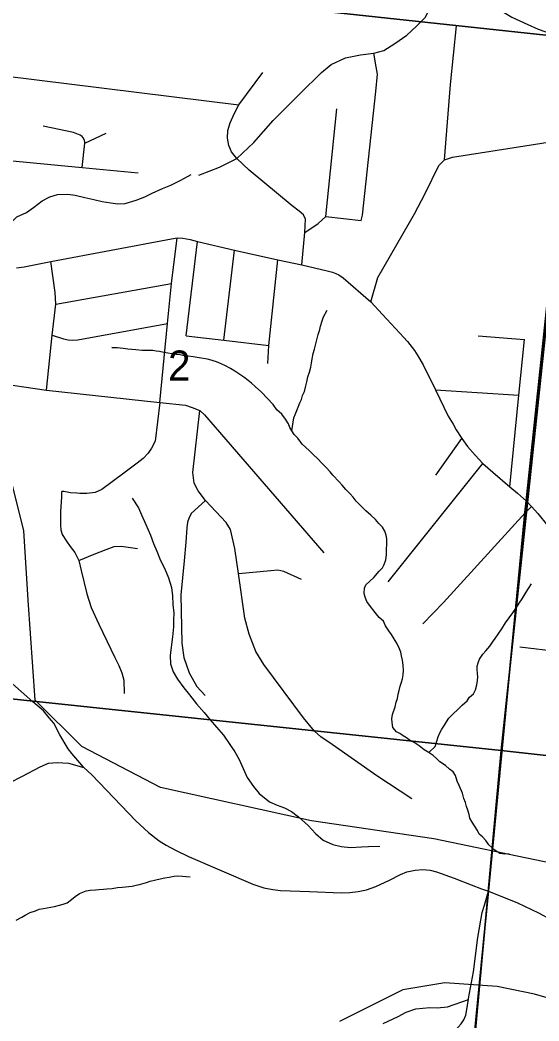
# Model space of a CAD drawing. Extents: x 0 to 34, y -2 to 22.
# Drawn here: x 6.671 to 7.396, y 18.207 to 19.604 of the extents above; entities that cross this region are included whole.
import ezdxf

# ---------------------------------------------------------------- set-up
doc = ezdxf.new("R2010")
doc.units = 0
for name, color, linetype in [('GM_X_City_Street', 7, 'Continuous'), ('GM_X_County_Road', 7, 'Continuous'), ('GM_X_Minor_River', 7, 'Continuous'), ('GM_X_Rail_Line', 7, 'Continuous'), ('GM_X_Section', 7, 'Continuous'), ('GM_X_Section_Text', 7, 'Continuous')]:
    doc.layers.add(name, color=color, linetype=linetype)

msp = doc.modelspace()

# ---------------------------------------------------------------- linework, layer by layer
at = {"layer": 'GM_X_City_Street'}
for p, q in [((7.0985, 19.3299), (7.1136, 19.4802)), ((6.7617, 19.4323), (6.7918, 19.4466)), ((6.9033, 19.1636), (6.9193, 19.2953)), ((6.9559, 19.1575), (6.9709, 19.2831)), ((6.7212, 19.208), (6.883, 19.2366)), ((7.3112, 19.1638), (7.376, 19.1583)), ((7.2517, 19.0883), (7.3679, 19.0806)), ((7.252, 18.9691), (7.2882, 19.0205)), ((7.1852, 18.8201), (7.3176, 18.9854)), ((7.4238, 18.7225), (7.3693, 18.729))]:
    msp.add_line(p, q, dxfattribs=at)
for points in [[(6.9742, 19.4112), (6.998, 19.4336), (7.0249, 19.464), (7.0622, 19.5013), (7.0924, 19.5313), (7.1056, 19.5424), (7.1256, 19.5517), (7.1468, 19.5559), (7.1652, 19.558), (7.1795, 19.562), (7.1948, 19.5714), (7.2114, 19.5834), (7.2252, 19.5956), (7.2369, 19.6078), (7.2495, 19.6321), (7.2627, 19.6641), (7.2673, 19.6719), (7.273, 19.6823)], [(6.4627, 19.5973), (6.4962, 19.5486), (6.4984, 19.547), (6.5001, 19.546), (6.5046, 19.5445), (6.5064, 19.5442), (6.9768, 19.4858)], [(7.2641, 19.4091), (7.2726, 19.5144), (7.2808, 19.5962)], [(7.1475, 19.3247), (7.1498, 19.3321), (7.168, 19.5045), (7.1706, 19.5287), (7.1688, 19.5392), (7.1652, 19.558)], [(7.0648, 19.2626), (7.069, 19.3078), (7.07, 19.3264), (7.067, 19.3325), (7.0612, 19.3377), (7.0515, 19.345), (6.9914, 19.3949), (6.9742, 19.4112), (6.9664, 19.4205), (6.9631, 19.4293), (6.9611, 19.4394), (6.9615, 19.4502), (6.9646, 19.4607), (6.9707, 19.4743), (6.9768, 19.4858), (7.0102, 19.5311)], [(6.758, 19.3985), (6.7617, 19.4323), (6.7618, 19.4334), (6.7613, 19.4366), (6.7597, 19.4399), (6.7583, 19.4419), (6.7552, 19.4438), (6.7458, 19.4475), (6.7035, 19.4561)], [(6.4991, 19.4022), (6.561, 19.4156), (6.5659, 19.4165), (6.5678, 19.4166), (6.583, 19.415), (6.656, 19.4082), (6.758, 19.3985), (6.8364, 19.3911)], [(6.9212, 19.3877), (6.95, 19.399), (6.9742, 19.4112)], [(7.069, 19.3078), (7.0876, 19.3204), (7.0985, 19.3299), (7.1475, 19.3247)], [(6.8667, 19.0705), (6.8771, 19.1808), (6.883, 19.2366), (6.8908, 19.3002)], [(6.7081, 19.0876), (6.7164, 19.1646), (6.7212, 19.208), (6.7205, 19.2239), (6.7144, 19.2672)], [(7.0174, 19.1251), (7.0189, 19.1501), (7.0314, 19.2698)], [(6.7164, 19.1646), (6.732, 19.1594), (6.7384, 19.1582), (6.7444, 19.1577), (6.7522, 19.1581), (6.8771, 19.1808)], [(6.9033, 19.1636), (6.9559, 19.1575), (7.0189, 19.1501)], [(7.3551, 18.953), (7.3679, 19.0806), (7.376, 19.1583)], [(6.6319, 19.0989), (6.7081, 19.0876), (6.8667, 19.0705), (6.9023, 19.0666), (6.9119, 19.0637), (6.9222, 19.0595), (6.929, 19.0535), (7.0954, 18.8607)], [(6.8667, 19.0705), (6.8599, 19.0164), (6.8548, 19.0067), (6.8502, 18.9999), (6.8431, 18.9925), (6.835, 18.986), (6.8162, 18.972), (6.7857, 18.9492), (6.7763, 18.9451), (6.7645, 18.9434), (6.755, 18.9437), (6.7504, 18.9438), (6.7417, 18.9445), (6.7327, 18.9462), (6.7298, 18.9464), (6.729, 18.9454), (6.7292, 18.9438), (6.729, 18.9391), (6.728, 18.9179), (6.7277, 18.8993), (6.7281, 18.8929), (6.73, 18.8863), (6.7361, 18.8772), (6.7411, 18.8696), (6.7478, 18.861), (6.7533, 18.8502), (6.7565, 18.8362), (6.7644, 18.8036), (6.7707, 18.7846), (6.7813, 18.761), (6.8039, 18.7145), (6.8093, 18.7034), (6.8136, 18.6931), (6.8161, 18.6831), (6.8167, 18.6645)], [(7.2183, 18.5175), (7.1696, 18.5495), (7.1071, 18.5934), (7.0916, 18.6041), (7.0827, 18.6117), (7.0672, 18.6306), (7.0116, 18.7047), (7.0007, 18.7232), (6.9913, 18.7473), (6.9854, 18.7694), (6.9765, 18.8319), (6.9714, 18.8666), (6.9653, 18.8933), (6.9594, 18.9033), (6.9302, 18.934), (6.9202, 18.9471), (6.9146, 18.9578), (6.9127, 18.9729), (6.9222, 19.0595)], [(6.9302, 18.934), (6.9102, 18.9158), (6.9071, 18.9086), (6.9054, 18.9034), (6.9042, 18.8955), (6.9029, 18.8756), (6.9003, 18.8497), (6.896, 18.802), (6.8972, 18.7348), (6.9002, 18.7149), (6.9077, 18.6933), (6.9183, 18.674), (6.9298, 18.6617)], [(7.2336, 18.7618), (7.2627, 18.7914), (7.3767, 18.9165), (7.3857, 18.9254)], [(6.7533, 18.8502), (6.7747, 18.859), (6.7918, 18.8656), (6.8026, 18.8697), (6.8125, 18.87), (6.8352, 18.8667)], [(6.9765, 18.8319), (7.0214, 18.8363), (7.0312, 18.8368), (7.0355, 18.8363), (7.0392, 18.8351), (7.0639, 18.8238)], [(7.1783, 18.204), (7.1995, 18.2138), (7.2106, 18.2198), (7.2239, 18.2242), (7.2435, 18.2263), (7.2539, 18.2259), (7.2681, 18.227), (7.2974, 18.2376)]]:
    msp.add_lwpolyline(points, dxfattribs=at)
at = {"layer": 'GM_X_County_Road'}
for points in [[(7.3332, 19.6234), (7.3367, 19.6212), (7.358, 19.6082), (7.3805, 19.5981), (7.3948, 19.5917), (7.4121, 19.5856), (7.4378, 19.5807), (7.4469, 19.5805), (7.4654, 19.58)], [(7.1611, 19.2111), (7.171, 19.245), (7.2064, 19.3063), (7.2223, 19.3338), (7.2372, 19.3621), (7.256, 19.4011), (7.2598, 19.4051), (7.2641, 19.4091), (7.2753, 19.413), (7.4149, 19.4349), (7.4318, 19.4376), (7.4347, 19.4382)], [(6.6662, 19.2586), (6.6771, 19.26), (6.7144, 19.2672), (6.883, 19.299), (6.8908, 19.3002), (6.8987, 19.3001), (6.909, 19.2978), (6.9193, 19.2953), (6.9709, 19.2831), (7.0314, 19.2698), (7.0648, 19.2626), (7.1001, 19.2545), (7.1078, 19.2525), (7.1122, 19.2508), (7.1164, 19.2488), (7.1224, 19.2446), (7.1611, 19.2111), (7.1773, 19.1932), (7.2018, 19.1672), (7.2124, 19.1556), (7.2221, 19.143), (7.227, 19.1355), (7.2343, 19.1231), (7.2517, 19.0883), (7.2693, 19.0517), (7.276, 19.0402), (7.2806, 19.0324), (7.2882, 19.0205), (7.2964, 19.0091), (7.3067, 18.9969), (7.3176, 18.9854), (7.3318, 18.9732), (7.3551, 18.953), (7.3659, 18.9438), (7.3784, 18.9328), (7.3857, 18.9254)], [(6.7603, 18.5613), (6.7435, 18.5806), (6.7385, 18.587), (6.7271, 18.6067), (6.7185, 18.6232), (6.7122, 18.6306), (6.7042, 18.6402), (6.6894, 18.6529), (6.6115, 18.7214), (6.6091, 18.7254), (6.6065, 18.7305), (6.6048, 18.735), (6.6027, 18.7411), (6.6011, 18.7465), (6.6001, 18.7509), (6.5985, 18.7586), (6.5988, 18.7676), (6.6004, 18.7792), (6.6087, 18.8604), (6.6319, 19.0989), (6.6381, 19.1562), (6.6503, 19.2574)], [(7.3857, 18.9254), (7.3945, 18.9158), (7.4079, 18.8991)], [(6.6565, 18.5396), (6.6748, 18.5491), (6.6995, 18.5623), (6.7111, 18.567), (6.7233, 18.5683), (6.7389, 18.5674), (6.7603, 18.5613), (6.7716, 18.551), (6.833, 18.4869), (6.8509, 18.4706), (6.8657, 18.4589), (6.8755, 18.4528), (6.8882, 18.4456), (6.9064, 18.4371), (6.9962, 18.3985), (7.0116, 18.3934), (7.0242, 18.391), (7.035, 18.3895), (7.0755, 18.388), (7.1197, 18.3864), (7.132, 18.3867), (7.1435, 18.3881), (7.155, 18.3906), (7.1683, 18.3949), (7.1873, 18.4039), (7.2026, 18.4116), (7.2116, 18.4155), (7.2229, 18.4181), (7.234, 18.4189), (7.244, 18.4179), (7.2531, 18.4157), (7.2776, 18.4067), (7.3011, 18.3972), (7.3157, 18.3917), (7.3256, 18.3884)], [(6.9856, 17.9573), (7.0226, 18.0067), (7.0467, 18.0378), (7.1418, 18.131), (7.1464, 18.1366), (7.1534, 18.1418), (7.2731, 18.1903), (7.2789, 18.194), (7.2874, 18.2033), (7.291, 18.209), (7.2937, 18.2153), (7.2974, 18.2376), (7.2976, 18.2388), (7.3044, 18.2759), (7.3107, 18.324), (7.3167, 18.3587), (7.3199, 18.3688), (7.3256, 18.3884)], [(7.3256, 18.3884), (7.3661, 18.3725), (7.3954, 18.3583), (7.4126, 18.3489), (7.4304, 18.3369), (7.45, 18.3244), (7.466, 18.3158), (7.479, 18.3104), (7.4847, 18.308), (7.4922, 18.306), (7.5073, 18.3032), (7.5172, 18.3011), (7.5367, 18.3001), (7.5668, 18.3021), (7.5866, 18.3055), (7.6331, 18.3193), (7.6583, 18.3289), (7.6712, 18.3329)]]:
    msp.add_lwpolyline(points, dxfattribs=at)
at = {"layer": 'GM_X_Minor_River'}
for points in [[(6.6556, 19.3187), (6.6668, 19.3298), (6.6803, 19.3359), (6.69, 19.3425), (6.702, 19.3518), (6.7127, 19.3576), (6.7235, 19.3607), (6.7379, 19.3615), (6.7481, 19.3598), (6.7617, 19.3568), (6.7742, 19.3538), (6.7859, 19.3509), (6.798, 19.349), (6.8079, 19.348), (6.8182, 19.3485), (6.8335, 19.3527), (6.8454, 19.3574), (6.8557, 19.3625), (6.8703, 19.369), (6.8819, 19.374), (6.8961, 19.3809), (6.9103, 19.3889)], [(7.051, 19.0308), (7.0538, 19.049), (7.0562, 19.0547), (7.0587, 19.0618), (7.062, 19.0701), (7.0644, 19.0746), (7.066, 19.0803), (7.0685, 19.0859), (7.0706, 19.0939), (7.0719, 19.0995), (7.0732, 19.1064), (7.0757, 19.1131), (7.0774, 19.12), (7.0783, 19.1253), (7.0792, 19.1317), (7.0809, 19.1389), (7.0826, 19.1449), (7.0839, 19.1506), (7.0856, 19.1578), (7.0878, 19.1654), (7.0898, 19.1725), (7.0911, 19.1771), (7.0932, 19.1843), (7.0953, 19.1903), (7.1001, 19.1993)], [(7.051, 19.0308), (7.0481, 19.0355), (7.046, 19.0408), (7.042, 19.0471), (7.0368, 19.0544), (7.0301, 19.0603), (7.0246, 19.0677), (7.0084, 19.0849), (6.9998, 19.0928), (6.9946, 19.0975), (6.9898, 19.1014), (6.9838, 19.1058), (6.9782, 19.1094), (6.9715, 19.1141), (6.9651, 19.1178), (6.9584, 19.1217), (6.9524, 19.1246), (6.9456, 19.1271), (6.9351, 19.1304), (6.9305, 19.1313), (6.9241, 19.1326), (6.9188, 19.1335), (6.9131, 19.1344), (6.9059, 19.135), (6.9006, 19.1359), (6.8949, 19.1369), (6.8892, 19.1374), (6.8836, 19.1383), (6.8775, 19.1396), (6.8722, 19.1405), (6.8662, 19.1415), (6.8612, 19.1424), (6.8567, 19.1429), (6.8498, 19.1431), (6.8419, 19.1429), (6.8328, 19.1439), (6.8218, 19.145), (6.8153, 19.1459), (6.807, 19.1469), (6.7994, 19.1475), (6.8093, 19.1469)], [(7.3545, 18.4407), (7.3484, 18.4402), (7.3415, 18.4411), (7.3344, 18.4459), (7.3259, 18.4534), (7.3219, 18.4592), (7.3171, 18.4646), (7.3126, 18.4682), (7.3101, 18.4732), (7.3028, 18.4848), (7.2995, 18.4906), (7.2985, 18.4956), (7.2968, 18.5014), (7.295, 18.5068), (7.2933, 18.5122), (7.2911, 18.5179), (7.2891, 18.5252), (7.2848, 18.536), (7.2819, 18.5422), (7.2795, 18.5502), (7.2762, 18.5553), (7.271, 18.5589), (7.2654, 18.564), (7.2575, 18.5691), (7.2531, 18.5735), (7.2483, 18.5778), (7.2412, 18.5825), (7.2356, 18.5857), (7.2289, 18.5916), (7.2218, 18.596), (7.2165, 18.5985), (7.2109, 18.6024), (7.2064, 18.6052), (7.2019, 18.6084), (7.1971, 18.6108), (7.1919, 18.6171), (7.191, 18.6239), (7.1907, 18.6289), (7.1916, 18.6353), (7.1954, 18.6459), (7.1967, 18.6523), (7.1983, 18.6576), (7.1996, 18.6637), (7.2009, 18.6686), (7.2022, 18.6747), (7.2039, 18.6803), (7.2052, 18.6849), (7.2065, 18.6905), (7.207, 18.6966), (7.2064, 18.7039), (7.2055, 18.7111), (7.2041, 18.7169), (7.2031, 18.7219), (7.2014, 18.7269), (7.1974, 18.7346), (7.193, 18.7419), (7.1901, 18.747), (7.1864, 18.752), (7.1817, 18.759), (7.1788, 18.7652), (7.1729, 18.7703), (7.1674, 18.7777), (7.1593, 18.7878), (7.1556, 18.7929), (7.1531, 18.799), (7.1521, 18.804), (7.1523, 18.8113), (7.1543, 18.8162), (7.1653, 18.8265), (7.1727, 18.8351), (7.1774, 18.8399), (7.1798, 18.8444), (7.1823, 18.8512), (7.1829, 18.858), (7.1835, 18.8801), (7.1825, 18.8855), (7.1807, 18.8912), (7.1774, 18.8966), (7.1723, 18.9017), (7.1675, 18.9072), (7.1612, 18.9131), (7.1541, 18.9194), (7.1474, 18.9264), (7.1408, 18.9327), (7.1367, 18.9385), (7.1323, 18.9432), (7.1264, 18.9491), (7.1212, 18.955), (7.1172, 18.9596), (7.1083, 18.969), (7.1042, 18.9737), (7.0987, 18.98), (7.0924, 18.9862), (7.0876, 18.9913), (7.0802, 18.9984), (7.0754, 19.0031), (7.0698, 19.0082), (7.0654, 19.0125), (7.0591, 19.0207), (7.0543, 19.0258), (7.051, 19.0308)], [(6.8279, 18.9371), (6.8367, 18.9236), (6.841, 18.914), (6.8468, 18.9005), (6.8533, 18.8855), (6.8575, 18.874), (6.8622, 18.8629), (6.8676, 18.8502), (6.873, 18.8394), (6.8788, 18.8259), (6.883, 18.8125), (6.8843, 18.8007), (6.8847, 18.7885), (6.8859, 18.7767), (6.8857, 18.7672), (6.8855, 18.7577), (6.884, 18.7436), (6.883, 18.733), (6.8811, 18.7175), (6.8816, 18.7057), (6.8851, 18.6945), (6.8913, 18.6845), (6.9001, 18.6725), (6.9079, 18.6624), (6.9178, 18.65), (6.9286, 18.6379), (6.937, 18.6278), (6.9459, 18.6174), (6.9555, 18.6065), (6.9643, 18.5933), (6.9713, 18.5829), (6.9775, 18.5725), (6.9829, 18.5598), (6.9887, 18.5471), (6.9975, 18.5347), (7.0052, 18.525), (7.0198, 18.5132), (7.0303, 18.5088), (7.0408, 18.5051), (7.0506, 18.4999), (7.0603, 18.4925), (7.0737, 18.4803), (7.084, 18.4691), (7.0948, 18.4597), (7.108, 18.4536), (7.1197, 18.4507), (7.133, 18.4496), (7.1482, 18.4504), (7.1581, 18.4509), (7.174, 18.4513)], [(7.242, 18.582), (7.2509, 18.5906), (7.253, 18.5967), (7.2554, 18.6039), (7.2575, 18.6095), (7.2603, 18.6148), (7.2643, 18.6204), (7.267, 18.6249), (7.2702, 18.6301), (7.2765, 18.6364), (7.2823, 18.6416), (7.2886, 18.6483), (7.2956, 18.6542), (7.2988, 18.6594), (7.3046, 18.6638), (7.3074, 18.6694), (7.3091, 18.6766), (7.3101, 18.6827), (7.3106, 18.6876), (7.3103, 18.6922), (7.3097, 18.6979), (7.3098, 18.7025), (7.3111, 18.7074), (7.3131, 18.7123), (7.3175, 18.7191), (7.3218, 18.7239), (7.3273, 18.7306), (7.3309, 18.7362), (7.3348, 18.7414), (7.34, 18.7485), (7.344, 18.7549), (7.3495, 18.7631), (7.3546, 18.7702), (7.3594, 18.7769), (7.3645, 18.7844), (7.3685, 18.7904), (7.3725, 18.7967), (7.378, 18.8057), (7.3812, 18.811), (7.3856, 18.8173)], [(6.6659, 18.348), (6.674, 18.3523), (6.6787, 18.3553), (6.6856, 18.3589), (6.6929, 18.3613), (6.6979, 18.3635), (6.704, 18.3644), (6.7094, 18.3654), (6.7193, 18.3674), (6.7266, 18.3688), (6.7315, 18.3705), (6.7373, 18.3723), (6.7431, 18.3771), (6.7482, 18.3811), (6.7544, 18.3851), (6.7636, 18.3891), (6.7693, 18.39), (6.7766, 18.3906), (6.7815, 18.3908), (6.788, 18.3914), (6.7926, 18.3917), (6.8002, 18.3922), (6.8075, 18.3936), (6.8139, 18.3941), (6.8185, 18.3948), (6.8281, 18.3956), (6.8334, 18.397), (6.838, 18.398), (6.848, 18.4008), (6.853, 18.4026), (6.861, 18.4046), (6.8668, 18.406), (6.8733, 18.4073), (6.8794, 18.4083), (6.8866, 18.4096), (6.8912, 18.4099), (6.898, 18.4097), (6.9033, 18.4092), (6.909, 18.4086)]]:
    msp.add_lwpolyline(points, dxfattribs=at)
at = {"layer": 'GM_X_Rail_Line'}
for points in [[(7.2924, 18.0527), (7.3254, 18.3889), (7.3765, 18.917), (7.3781, 18.9333), (7.4316, 19.4382), (7.4466, 19.581), (7.5261, 20.3339), (7.5512, 20.5718), (7.5526, 20.5853), (7.5548, 20.6102), (7.5809, 20.9), (2.1, 20.9)], [(8.9, 16.3574), (8.9, 20.9), (7.5809, 20.9), (7.5548, 20.6102), (7.5526, 20.5853), (7.5512, 20.5718), (7.5261, 20.3339), (7.4466, 19.581), (7.4316, 19.4382), (7.3781, 18.9333), (7.3765, 18.917), (7.3254, 18.3889), (7.2924, 18.0527)], [(8.8934, 18.204), (8.7591, 18.2174), (8.7083, 18.2219), (8.48, 18.2189), (8.3337, 18.2323), (8.1621, 18.2816), (8.0547, 18.3219), (7.8696, 18.3772), (7.7965, 18.3995), (7.7368, 18.4025), (7.5538, 18.3982), (7.2492, 18.4615), (7.0783, 18.4868), (6.8673, 18.5333), (6.7576, 18.5903), (6.6926, 18.6551), (6.6825, 18.7945), (6.6766, 18.8917), (6.6605, 18.9564)], [(7.9414, 18.1945), (7.8552, 18.2209), (7.7713, 18.2526), (7.708, 18.2589), (7.6526, 18.2478), (7.5655, 18.2209), (7.5243, 18.2177), (7.4563, 18.2256), (7.3898, 18.2446), (7.3375, 18.2557), (7.2647, 18.2605), (7.2061, 18.251), (7.1174, 18.2066)]]:
    msp.add_lwpolyline(points, dxfattribs=at)
at = {"layer": 'GM_X_Section'}
for points in [[(6.545, 20.6847), (7.556, 20.5828), (7.4489, 19.5784), (6.443, 19.687)], [(7.4489, 19.5784), (7.3433, 18.5849), (6.3407, 18.6907), (6.443, 19.687)], [(7.4489, 19.5784), (8.4442, 19.5041), (8.3344, 18.4751), (7.3433, 18.5849)], [(7.3433, 18.5849), (7.2505, 17.5778), (6.241, 17.6971), (6.3407, 18.6907)], [(8.3344, 18.4751), (8.2288, 17.4754), (7.2505, 17.5778), (7.3433, 18.5849)]]:
    msp.add_lwpolyline(points, close=True, dxfattribs=at)

# ---------------------------------------------------------------- texts
at = {"layer": 'GM_X_Section_Text'}
msp.add_text('2', height=0.0419, rotation=0, dxfattribs=at).set_placement((6.8781, 19.1012))

doc.saveas('drawing.dxf')
